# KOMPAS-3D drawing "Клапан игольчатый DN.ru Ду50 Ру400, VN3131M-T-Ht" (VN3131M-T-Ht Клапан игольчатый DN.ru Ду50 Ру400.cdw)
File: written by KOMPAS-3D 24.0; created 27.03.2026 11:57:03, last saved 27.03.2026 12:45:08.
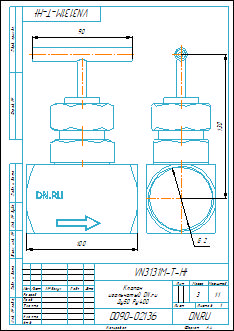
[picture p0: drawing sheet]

Document properties: Автор: Илья; Форматы листов документа: A4; Полное имя файла: VN3131M-T-Ht Клапан игольчатый DN.ru Ду50 Ру400.m3d; Масса: 3; Наименование: Клапан игольчатый DN.ru Ду50 Ру400; Количество листов документа: 1; Примечание: D090-02136

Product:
- Body: Body1  | qty 1
    Масса: 2.961611
- Part/product: Клапан игольчатый DN.ru Ду50 Ру400  | designation VN3131M-T-Ht
    Масса: 3
    Раздел спецификации: Прочие изделия
    Примечание: D090-02136

Views: Вид 1, Слева, Проекционный вид 2
Referenced files in D:\Обмен\Заказы с фриланса\DN.ru\VNxxM-T-Ht Клапан игольчатый DN.ru Ду8-50 Ру400\VN3232M-T-Ht Клапан игольчатый DN.ru Ду8-50 Ру400\DN8\: VN3232M-T-Ht Клапан игольчатый DN.ru Ду8 Ру400.m3d, VN3232M-T-Ht Клапан игольчатый DN.ru Ду8 Ру400.cdw
Referenced files in D:\Обмен\Заказы с фриланса\DN.ru\VNxxM-T-Ht Клапан игольчатый DN.ru Ду8-50 Ру400\VN3131M-T-Ht Клапан игольчатый DN.ru Ду8-50 Ру400\DN50\: VN3131M-T-Ht Клапан игольчатый DN.ru Ду50 Ру400.m3d
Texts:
  VN3131M-T-Ht
  Клапан
  игольчатый DN.ru
  Ду50 Ру400
  Body1
  Клапан игольчатый DN.ru Ду50 Ру400
  VN3131M-T-Ht Клапан игольчатый DN.ru Ду50 Ру400
Dimensions and other numbers on the sheet: 0; 3; 2; 4; 90; 100; 130; 1:1; 1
